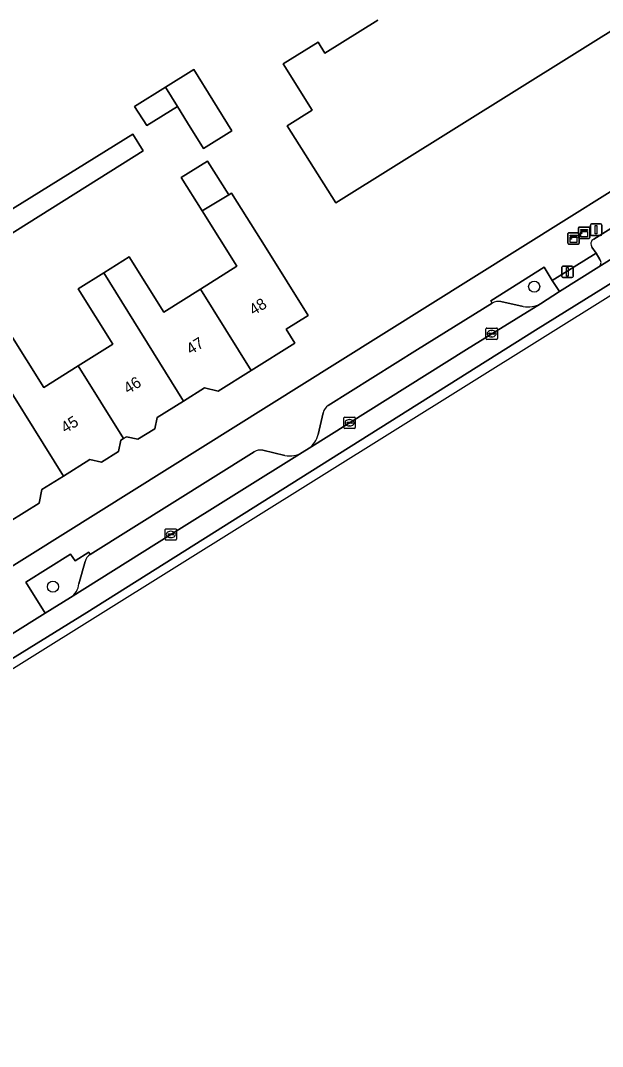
# Model space of a CAD drawing. Extents: x 159352 to 160617, y 385888 to 387323.
# Drawn here: x 159801.4 to 159852.7, y 385938.7 to 386029 of the extents above; entities that cross this region are included whole.
import ezdxf

# ---------------------------------------------------------------- set-up
doc = ezdxf.new("R2010")
doc.units = 0
for name, color, linetype in [('IMGEO_Boom', 7, 'Continuous'), ('IMGEO_Erf', 7, 'Continuous'), ('IMGEO_Fietspad_open', 7, 'Continuous'), ('IMGEO_Groenvoorziening', 7, 'Continuous'), ('IMGEO_Kast', 7, 'Continuous'), ('IMGEO_Kolk', 7, 'Continuous'), ('IMGEO_Lichtmast', 7, 'Continuous'), ('IMGEO_Pand', 7, 'Continuous'), ('IMGEO_Pand_nummerreeks', 7, 'Continuous'), ('IMGEO_Parkeervlak_open', 7, 'Continuous'), ('IMGEO_Rijbaan_regionaal_gesloten', 7, 'Continuous'), ('IMGEO_Verkeersregelinstallatiepaal', 7, 'Continuous'), ('IMGEO_Voetpad_open', 7, 'Continuous')]:
    doc.layers.add(name, color=color, linetype=linetype)

msp = doc.modelspace()

# ---------------------------------------------------------------- linework, layer by layer
at = {"layer": 'IMGEO_Boom'}
for centre in [(159846.653, 386005.544), (159804.27, 385979.138)]:
    msp.add_circle(centre, 0.489, dxfattribs=at)
at = {"layer": 'IMGEO_Erf'}
for points in [[(159860.819, 386032.682), (159829.198, 386012.912), (159824.894, 386019.704), (159827.088, 386021.068), (159824.557, 386025.141), (159827.618, 386027.043), (159828.216, 386026.081), (159832.89, 386028.986)], [(159796.167, 385978.135), (159829.32, 385998.863), (159873.502, 386026.485)], [(159782.041, 386000.826), (159811.303, 386018.953), (159812.211, 386017.488), (159785.725, 386000.86)], [(159800.406, 386001.547), (159803.461, 385996.676), (159806.504, 385998.584), (159809.544, 386000.49), (159806.494, 386005.353), (159808.741, 386006.762), (159810.985, 386008.169), (159814.039, 386003.297), (159817.26, 386005.317), (159820.478, 386007.335), (159817.423, 386012.206), (159815.574, 386015.154), (159817.876, 386016.598), (159819.752, 386013.607), (159819.997, 386013.754), (159823.055, 386008.918), (159826.74, 386003.004), (159824.824, 386001.801), (159825.588, 386000.58), (159821.719, 385998.161), (159818.835, 385996.357), (159817.633, 385996.637), (159815.775, 385995.473), (159813.465, 385994.025), (159813.245, 385993.04), (159811.757, 385992.111), (159810.747, 385992.332), (159810.497, 385992.174), (159810.262, 385992.024), (159810.042, 385991.036), (159808.536, 385990.104), (159807.536, 385990.327), (159805.188, 385988.864), (159803.3, 385987.688), (159803.052, 385986.476), (159800.428, 385984.839)]]:
    msp.add_lwpolyline(points, dxfattribs=at)
msp.add_lwpolyline([(159811.462, 386021.404), (159814.173, 386023.092), (159816.676, 386024.65), (159820.038, 386019.266), (159817.535, 386017.705), (159816.137, 386019.945), (159815.231, 386021.396), (159812.537, 386019.717)], close=True, dxfattribs=at)
at = {"layer": 'IMGEO_Fietspad_open'}
for points in [[(159732.868, 385930.223), (159789.753, 385966.056), (159807.266, 385976.872), (159846.766, 386001.708), (159890.661, 386028.937)], [(159861.026, 386012.714), (159852.337, 386007.274), (159848.877, 386005.124), (159847.204, 386004.039), (159842.911, 386001.399), (159840.679, 386000), (159826.846, 385991.331), (159826.23, 385990.945), (159814.656, 385983.733), (159805.827, 385978.178), (159803.584, 385976.806), (159800.461, 385974.853), (159797.711, 385973.111), (159788.825, 385967.561), (159787.886, 385966.974), (159786.644, 385966.207), (159786.554, 385966.152), (159784.029, 385964.604), (159777.24, 385960.333), (159775.972, 385959.527), (159769.2, 385955.252), (159767.426, 385954.133), (159743.553, 385939.2)]]:
    msp.add_lwpolyline(points, dxfattribs=at)
at = {"layer": 'IMGEO_Groenvoorziening'}
for points in [[(159847.204, 386004.039), (159848.877, 386005.124), (159848.251, 386006.088), (159847.539, 386007.254), (159842.827, 386004.297), (159842.95, 386004.102)], [(159843.72, 386004.232), (159845.682, 386003.803)], [(159807.551, 385981.977), (159807.431, 385982.161), (159806.226, 385981.402), (159805.819, 385982.005), (159801.872, 385979.534), (159803.584, 385976.806), (159805.827, 385978.178)], [(159806.567, 385979.401), (159807.12, 385981.355)]]:
    msp.add_lwpolyline(points, dxfattribs=at)
for centre, radius, start, end in [((159843.539, 386002.961), 1.284, 81.87322, 117.29267), ((159846.126, 386005.967), 2.209, 258.40854, 299.21954), ((159808.017, 385981.194), 0.911, 120.75212, 169.80968), ((159804.911, 385979.568), 1.664, 303.38878, 354.25751)]:
    msp.add_arc(centre, radius, start, end, dxfattribs=at)
at = {"layer": 'IMGEO_Kast'}
for p, q in [((159850.558, 386009.865), (159850.558, 386010.706)), ((159850.558, 386010.706), (159850.558, 386009.865)), ((159850.633, 386010.79), (159851.474, 386010.79)), ((159851.474, 386010.79), (159850.633, 386010.79)), ((159851.558, 386010.715), (159851.558, 386009.874)), ((159851.558, 386009.874), (159851.558, 386010.715)), ((159849.629, 386009.363), (159849.629, 386010.204)), ((159849.629, 386010.204), (159849.629, 386009.363)), ((159849.704, 386010.288), (159850.545, 386010.288)), ((159850.545, 386010.288), (159849.704, 386010.288)), ((159850.629, 386010.213), (159850.629, 386009.372)), ((159850.629, 386009.372), (159850.629, 386010.213)), ((159851.483, 386009.79), (159850.642, 386009.79)), ((159850.642, 386009.79), (159851.483, 386009.79)), ((159850.554, 386009.288), (159849.713, 386009.288)), ((159849.713, 386009.288), (159850.554, 386009.288))]:
    msp.add_line(p, q, dxfattribs=at)
for points in [[(159849.824, 386010.078), (159850.424, 386010.078), (159850.424, 386009.993), (159849.824, 386009.993), (159849.824, 386010.078)], [(159849.824, 386009.903), (159850.424, 386009.903), (159850.424, 386009.414), (159849.824, 386009.414), (159849.824, 386009.903)], [(159850.753, 386010.58), (159851.353, 386010.58), (159851.353, 386010.495), (159850.753, 386010.495), (159850.753, 386010.58)], [(159850.753, 386010.405), (159851.353, 386010.405), (159851.353, 386009.916), (159850.753, 386009.916), (159850.753, 386010.405)]]:
    msp.add_lwpolyline(points, dxfattribs=at)
for centre in [(159849.908, 386009.752), (159850.837, 386010.254)]:
    msp.add_circle(centre, 0.0377, dxfattribs=at)
for centre, start, end in [((159850.636, 386010.712), 92.4484, 184.28452), ((159850.636, 386010.712), 92.4484, 184.28452), ((159851.48, 386010.712), 2.4484, 94.28452), ((159851.48, 386010.712), 2.4484, 94.28452), ((159849.707, 386010.21), 92.4484, 184.28452), ((159849.707, 386010.21), 92.4484, 184.28452), ((159850.551, 386010.21), 2.4484, 94.28452), ((159850.551, 386010.21), 2.4484, 94.28452), ((159850.636, 386009.868), 182.4484, 274.28452), ((159850.636, 386009.868), 182.4484, 274.28452), ((159851.48, 386009.868), 272.4484, 4.28452), ((159851.48, 386009.868), 272.4484, 4.28452), ((159849.707, 386009.366), 182.4484, 274.28452), ((159849.707, 386009.366), 182.4484, 274.28452), ((159850.551, 386009.366), 272.4484, 4.28452), ((159850.551, 386009.366), 272.4484, 4.28452)]:
    msp.add_arc(centre, 0.0779, start, end, dxfattribs=at)
at = {"layer": 'IMGEO_Kolk'}
for p, q in [((159842.41, 386000.975), (159842.41, 386001.827)), ((159842.485, 386001.901), (159843.337, 386001.901)), ((159842.898, 386001.681), (159842.923, 386001.681)), ((159843.411, 386001.827), (159843.411, 386000.975)), ((159843.337, 386000.901), (159842.485, 386000.901)), ((159842.669, 386001.395), (159842.669, 386001.407)), ((159843.107, 386001.358), (159842.709, 386001.358)), ((159842.712, 386001.444), (159843.11, 386001.444)), ((159842.921, 386001.121), (159842.896, 386001.121)), ((159843.153, 386001.407), (159843.153, 386001.395)), ((159829.897, 385993.133), (159829.897, 385993.985)), ((159829.972, 385994.059), (159830.824, 385994.059)), ((159830.156, 385993.553), (159830.156, 385993.565)), ((159830.594, 385993.516), (159830.196, 385993.516)), ((159830.199, 385993.602), (159830.597, 385993.602)), ((159830.385, 385993.839), (159830.41, 385993.839)), ((159830.64, 385993.565), (159830.64, 385993.553)), ((159830.898, 385993.985), (159830.898, 385993.133)), ((159830.824, 385993.059), (159829.972, 385993.059)), ((159830.408, 385993.279), (159830.383, 385993.279)), ((159814.154, 385983.308), (159814.154, 385984.16)), ((159814.229, 385984.234), (159815.081, 385984.234)), ((159814.413, 385983.728), (159814.413, 385983.74)), ((159814.851, 385983.691), (159814.453, 385983.691)), ((159814.456, 385983.777), (159814.854, 385983.777)), ((159814.642, 385984.014), (159814.667, 385984.014)), ((159814.897, 385983.74), (159814.897, 385983.728)), ((159815.155, 385984.16), (159815.155, 385983.308)), ((159815.081, 385983.234), (159814.229, 385983.234)), ((159814.665, 385983.454), (159814.64, 385983.454))]:
    msp.add_line(p, q, dxfattribs=at)
for points in [[(159842.41, 386000.975), (159842.41, 386001.827)], [(159842.485, 386001.901), (159843.337, 386001.901)], [(159843.411, 386001.827), (159843.411, 386000.975)], [(159843.337, 386000.901), (159842.485, 386000.901)], [(159829.897, 385993.133), (159829.897, 385993.985)], [(159829.972, 385994.059), (159830.824, 385994.059)], [(159830.898, 385993.985), (159830.898, 385993.133)], [(159830.824, 385993.059), (159829.972, 385993.059)], [(159814.154, 385983.308), (159814.154, 385984.16)], [(159814.229, 385984.234), (159815.081, 385984.234)], [(159815.155, 385984.16), (159815.155, 385983.308)], [(159815.081, 385983.234), (159814.229, 385983.234)]]:
    msp.add_lwpolyline(points, dxfattribs=at)
for centre, radius, start, end in [((159842.487, 386001.825), 0.0765, 91.55205, 178.44795), ((159842.487, 386001.825), 0.0765, 91.55205, 178.44795), ((159843.335, 386001.825), 0.0765, 1.55205, 88.44795), ((159843.335, 386001.825), 0.0765, 1.55205, 88.44795), ((159842.487, 386000.977), 0.0765, 181.55205, 268.44795), ((159842.487, 386000.977), 0.0765, 181.55205, 268.44795), ((159842.709, 386001.404), 0.0403, 85.87752, 175.75265), ((159842.706, 386001.394), 0.0366, 178.93798, 274.71019), ((159843.11, 386001.401), 0.043, 264.86636, 352.45326), ((159843.114, 386001.406), 0.0386, 1.73085, 96.63898), ((159843.335, 386000.977), 0.0765, 271.55205, 358.44795), ((159843.335, 386000.977), 0.0765, 271.55205, 358.44795), ((159829.974, 385993.983), 0.0765, 91.55205, 178.44795), ((159829.974, 385993.983), 0.0765, 91.55205, 178.44795), ((159830.196, 385993.562), 0.0403, 85.87752, 175.75265), ((159830.193, 385993.552), 0.0366, 178.93798, 274.71019), ((159830.597, 385993.559), 0.043, 264.86636, 352.45326), ((159830.601, 385993.564), 0.0386, 1.73085, 96.63898), ((159830.822, 385993.983), 0.0765, 1.55205, 88.44795), ((159830.822, 385993.983), 0.0765, 1.55205, 88.44795), ((159829.974, 385993.135), 0.0765, 181.55205, 268.44795), ((159829.974, 385993.135), 0.0765, 181.55205, 268.44795), ((159830.822, 385993.135), 0.0765, 271.55205, 358.44795), ((159830.822, 385993.135), 0.0765, 271.55205, 358.44795), ((159814.231, 385984.158), 0.0765, 91.55205, 178.44795), ((159814.231, 385984.158), 0.0765, 91.55205, 178.44795), ((159814.453, 385983.737), 0.0403, 85.87752, 175.75265), ((159814.45, 385983.727), 0.0366, 178.93798, 274.71019), ((159814.854, 385983.734), 0.043, 264.86636, 352.45326), ((159814.858, 385983.739), 0.0386, 1.73085, 96.63898), ((159815.079, 385984.158), 0.0765, 1.55205, 88.44795), ((159815.079, 385984.158), 0.0765, 1.55205, 88.44795), ((159814.231, 385983.31), 0.0765, 181.55205, 268.44795), ((159814.231, 385983.31), 0.0765, 181.55205, 268.44795), ((159815.079, 385983.31), 0.0765, 271.55205, 358.44795), ((159815.079, 385983.31), 0.0765, 271.55205, 358.44795)]:
    msp.add_arc(centre, radius, start, end, dxfattribs=at)
for centre, major_axis, ratio, start_param, end_param in [((159842.897, 386001.401), (-0.387, 0.002), 0.722429, 4.712389, 7.853982), ((159842.922, 386001.401), (-0.39, 0.002), 0.717154, 1.570796, 4.712389), ((159830.384, 385993.559), (-0.387, 0.002), 0.722429, 4.712389, 7.853982), ((159830.409, 385993.559), (-0.39, 0.002), 0.717154, 1.570796, 4.712389), ((159814.641, 385983.734), (-0.387, 0.002), 0.722429, 4.712389, 7.853982), ((159814.666, 385983.734), (-0.39, 0.002), 0.717154, 1.570796, 4.712389)]:
    msp.add_ellipse(centre, major_axis=major_axis, ratio=ratio, start_param=start_param, end_param=end_param, dxfattribs=at)
at = {"layer": 'IMGEO_Lichtmast'}
for p, q in [((159851.61, 386010.157), (159851.61, 386010.957)), ((159851.61, 386010.957), (159851.61, 386010.157)), ((159851.71, 386011.057), (159852.5, 386011.057)), ((159852.5, 386011.057), (159851.71, 386011.057)), ((159852.6, 386010.957), (159852.6, 386010.157)), ((159852.6, 386010.157), (159852.6, 386010.957)), ((159852.5, 386010.057), (159851.71, 386010.057)), ((159851.71, 386010.057), (159852.5, 386010.057))]:
    msp.add_line(p, q, dxfattribs=at)
msp.add_lwpolyline([(159852.03, 386010.932), (159852.18, 386010.932), (159852.18, 386010.182), (159852.03, 386010.182), (159852.03, 386010.932)], dxfattribs=at)
for centre, start, end in [((159851.71, 386010.957), 90, 180), ((159851.71, 386010.957), 90, 180), ((159852.5, 386010.957), 0, 90), ((159852.5, 386010.957), 360, 90), ((159851.71, 386010.157), 180, 270), ((159851.71, 386010.157), 180, 270), ((159852.5, 386010.157), 270, 0), ((159852.5, 386010.157), 270, 0)]:
    msp.add_arc(centre, 0.1, start, end, dxfattribs=at)
at = {"layer": 'IMGEO_Pand'}
msp.add_lwpolyline([(159832.89, 386028.986), (159828.216, 386026.081), (159827.618, 386027.043), (159824.557, 386025.141), (159827.088, 386021.068), (159824.894, 386019.704), (159829.198, 386012.912), (159860.819, 386032.682)], dxfattribs=at)
for points in [[(159814.173, 386023.092), (159815.231, 386021.396), (159816.137, 386019.945), (159817.535, 386017.705), (159820.038, 386019.266), (159816.676, 386024.65)], [(159811.462, 386021.404), (159812.537, 386019.717), (159815.231, 386021.396), (159814.173, 386023.092)], [(159817.423, 386012.206), (159819.752, 386013.607), (159817.876, 386016.598), (159815.574, 386015.154)], [(159823.055, 386008.918), (159819.997, 386013.754), (159819.752, 386013.607), (159817.423, 386012.206), (159820.478, 386007.335), (159817.26, 386005.317), (159821.719, 385998.161), (159825.588, 386000.58), (159824.824, 386001.801), (159826.74, 386003.004)], [(159815.775, 385995.473), (159817.633, 385996.637), (159818.835, 385996.357), (159821.719, 385998.161), (159817.26, 386005.317), (159814.039, 386003.297), (159810.985, 386008.169), (159808.741, 386006.762)], [(159810.497, 385992.174), (159810.747, 385992.332), (159811.757, 385992.111), (159813.245, 385993.04), (159813.465, 385994.025), (159815.775, 385995.473), (159808.741, 386006.762), (159806.494, 386005.353), (159809.544, 386000.49), (159806.504, 385998.584)], [(159806.504, 385998.584), (159803.461, 385996.676), (159800.406, 386001.547), (159798.162, 386000.14), (159805.188, 385988.864), (159807.536, 385990.327), (159808.536, 385990.104), (159810.042, 385991.036), (159810.262, 385992.024), (159810.497, 385992.174)], [(159798.162, 386000.14), (159795.916, 385998.731), (159797.637, 385995.987), (159794.649, 385994.113), (159795.977, 385991.982), (159800.428, 385984.839), (159803.052, 385986.476), (159803.3, 385987.688), (159805.188, 385988.864)]]:
    msp.add_lwpolyline(points, close=True, dxfattribs=at)
at = {"layer": 'IMGEO_Parkeervlak_open'}
for points in [[(159856.818, 386012.798), (159851.896, 386009.727)], [(159852.337, 386007.274), (159861.026, 386012.714)], [(159851.744, 386009.007), (159852.106, 386008.498), (159852.448, 386007.936)], [(159826.846, 385991.331), (159840.679, 386000), (159842.911, 386001.399), (159847.204, 386004.039)], [(159842.95, 386004.102), (159836.386, 386000), (159828.523, 385995.086)], [(159845.682, 386003.803), (159843.72, 386004.232)], [(159828.074, 385994.447), (159827.618, 385992.518)], [(159805.827, 385978.178), (159814.656, 385983.733), (159826.23, 385990.945)], [(159821.981, 385991.005), (159807.551, 385981.977)], [(159824.707, 385990.694), (159822.75, 385991.153)], [(159807.12, 385981.355), (159806.567, 385979.401)]]:
    msp.add_lwpolyline(points, dxfattribs=at)
for centre, radius, start, end in [((159852.136, 386009.3), 0.49, 119.38125, 216.77728), ((159852.079, 386007.658), 0.462, 303.8914, 37.07169), ((159843.539, 386002.961), 1.284, 81.87322, 117.29267), ((159846.126, 386005.967), 2.209, 258.40854, 299.21954), ((159829.112, 385994.195), 1.068, 123.46263, 166.34898), ((159825.516, 385993.04), 2.166, 307.87892, 346.04281), ((159822.589, 385989.916), 1.247, 82.5971, 119.19054), ((159825.159, 385992.698), 2.054, 257.28846, 301.4287), ((159808.017, 385981.194), 0.911, 120.75212, 169.80968), ((159804.911, 385979.568), 1.664, 303.38878, 354.25751)]:
    msp.add_arc(centre, radius, start, end, dxfattribs=at)
at = {"layer": 'IMGEO_Rijbaan_regionaal_gesloten'}
for points in [[(159680.589, 385901.515), (159678.374, 385900.403), (159677.09, 385899.832), (159676.054, 385899.376), (159674.34, 385898.621), (159673.604, 385898.41), (159672.377, 385898.152), (159671.133, 385898.005), (159669.88, 385897.969), (159668.841, 385898.033), (159672.265, 385892.74), (159701.42, 385910.447), (159730.336, 385928.01), (160003.316, 386098.383), (160029.667, 386114.83), (160338.731, 386306.963), (160519.651, 386421.283), (160554.007, 386449.857), (160584.37, 386476.501)], [(160004.347, 386101.103), (160002.357, 386099.871), (159999.724, 386098.31), (159991.642, 386093.359), (159989.333, 386091.543), (159985.375, 386088.326), (159946.201, 386063.73), (159920.298, 386047.584), (159890.661, 386028.937), (159846.766, 386001.708), (159807.266, 385976.872), (159789.753, 385966.056), (159732.868, 385930.223), (159726.624, 385926.948)]]:
    msp.add_lwpolyline(points, dxfattribs=at)
at = {"layer": 'IMGEO_Verkeersregelinstallatiepaal'}
for p, q in [((159849.089, 386006.443), (159849.089, 386007.243)), ((159849.089, 386007.243), (159849.089, 386006.443)), ((159849.189, 386007.343), (159849.979, 386007.343)), ((159849.979, 386007.343), (159849.189, 386007.343)), ((159850.079, 386007.243), (159850.079, 386006.443)), ((159850.079, 386006.443), (159850.079, 386007.243)), ((159849.979, 386006.343), (159849.189, 386006.343)), ((159849.189, 386006.343), (159849.979, 386006.343))]:
    msp.add_line(p, q, dxfattribs=at)
msp.add_lwpolyline([(159849.509, 386007.218), (159849.659, 386007.218), (159849.659, 386006.468), (159849.509, 386006.468), (159849.509, 386007.218)], dxfattribs=at)
for centre, start, end in [((159849.189, 386007.243), 90, 180), ((159849.189, 386007.243), 90, 180), ((159849.979, 386007.243), 0, 90), ((159849.979, 386007.243), 360, 90), ((159849.189, 386006.443), 180, 270), ((159849.189, 386006.443), 180, 270), ((159849.979, 386006.443), 270, 0), ((159849.979, 386006.443), 270, 0)]:
    msp.add_arc(centre, 0.1, start, end, dxfattribs=at)
at = {"layer": 'IMGEO_Voetpad_open'}
for points in [[(159873.502, 386026.485), (159829.32, 385998.863), (159796.167, 385978.135), (159794.607, 385977.16), (159792.94, 385976.214), (159797.16, 385973.993), (159797.711, 385973.111), (159800.461, 385974.853), (159803.584, 385976.806), (159801.872, 385979.534), (159805.819, 385982.005), (159806.226, 385981.402), (159807.431, 385982.161), (159807.551, 385981.977), (159821.981, 385991.005)], [(159851.896, 386009.727), (159856.818, 386012.798)], [(159828.523, 385995.086), (159836.386, 386000), (159842.95, 386004.102), (159842.827, 386004.297), (159847.539, 386007.254), (159848.251, 386006.088), (159852.106, 386008.498), (159851.744, 386009.007)], [(159852.448, 386007.936), (159852.106, 386008.498), (159848.251, 386006.088), (159848.877, 386005.124), (159852.337, 386007.274)], [(159827.618, 385992.518), (159828.074, 385994.447)], [(159822.75, 385991.153), (159824.707, 385990.694)], [(159826.23, 385990.945), (159826.846, 385991.331)]]:
    msp.add_lwpolyline(points, dxfattribs=at)
msp.add_lwpolyline([(159812.211, 386017.488), (159811.303, 386018.953), (159782.041, 386000.826), (159783.057, 385999.185), (159785.725, 386000.86)], close=True, dxfattribs=at)
for centre, radius, start, end in [((159852.136, 386009.3), 0.49, 119.38125, 216.77728), ((159852.079, 386007.658), 0.462, 303.8914, 37.07169), ((159829.112, 385994.195), 1.068, 123.46263, 166.34898), ((159825.516, 385993.04), 2.166, 307.87892, 346.04281), ((159822.589, 385989.916), 1.247, 82.5971, 119.19054), ((159825.159, 385992.698), 2.054, 257.28846, 301.4287)]:
    msp.add_arc(centre, radius, start, end, dxfattribs=at)

# ---------------------------------------------------------------- texts
at = {"layer": 'IMGEO_Pand_nummerreeks'}
for s, rotation, p in [('48', 32.02834, (159821.944, 386002.976)), ('47', 32.02601, (159816.415, 385999.519)), ('46', 32.02601, (159810.889, 385996.062)), ('45', 32.02601, (159805.364, 385992.606))]:
    msp.add_text(s, height=1, rotation=rotation, dxfattribs=at).set_placement(p)

doc.saveas('drawing.dxf')
